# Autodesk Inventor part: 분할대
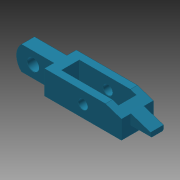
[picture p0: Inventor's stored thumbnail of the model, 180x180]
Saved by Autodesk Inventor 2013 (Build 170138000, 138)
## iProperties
Created: 2016-11
Part Number: 분할대
Material: 강철, 연강
Document SubType Name: Modeling
Designer: mduedu
Density: 1 g/cm^3
Author: mduedu
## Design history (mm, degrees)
sketch "스케치1"
  geometry: L1 (32.5, 13.5)-(-32.5, 13.5); L2 (-32.5, 13.5)-(-32.5, -13.5); L3 (-32.5, -13.5)-(32.5, -13.5); L4 (32.5, -13.5)-(32.5, 13.5); L5 (24, 7.5)-(-24, 7.5); L6 (-24, 7.5)-(-24, -7.5); L7 (-24, -7.5)-(24, -7.5); L8 (24, -7.5)-(24, 7.5); L9 (24, 0)-(-24, 0); L10 (0, -13.5)-(0, 13.5); 4 further points
  constraints: 20 end point, 7 midpoint, 4 parallel, 2 coincident, 2 horizontal, 2 perpendicular, 1 horizontal alignment
  dimensions: "d0" = 15 distance of L5.end L6.end; "d2" = 27 distance between parallel lines of L1 L3; "d3" = 48 distance of L5.start L5.end; "d4" = 65 distance of L1.start L1.end
extrude "돌출1" new body sketch "스케치1" distance "d5" = 20; taper "d6" = 0 deg
sketch "스케치2"
  geometry: L1 (0, 0)-(65, 0) reference; L2 (65, 0)-(65, 20) reference; L3 (0, 20)-(65, 20) reference; L4 (0, 0)-(0, 20) reference; L5 (32.5, 0)-(32.5, 20); C1 r 4 at (32.5, 10)
  constraints: 2 end point, 2 midpoint, 1 centre point
  dimensions: "d7" = 8 diameter of C1
extrude "돌출2" cut sketch "스케치2" stored distance "d8" = 20; taper "d9" = 0 deg
chamfer "모따기1" distance "d10" = 0.2; stored, may be unused: second distance "d11" = 2, angle "d12" = 45 deg
sketch "스케치3"
  geometry: L1 (-32.5, 0)-(-32.5, 20) reference; L2 (-32.5, 20)-(-59.798, 20); L3 (-64, 20)-(-64, 0); L4 (-64, 0)-(-59.798, 0); L5 (-32.5, 0)-(-32.5, 20); L6 (-59.798, 20)-(-64, 20); L7 (-59.798, 0)-(-32.5, 0); C1 r 4.2 at (0, 10) reference; C2 r 5 at (-50, 10); A1 r 14 centre (-50, 10) between (-59.798, 20) and (-59.798, 0); 1 further point
  constraints: 12 end point, 5 parallel, 2 centre point, 2 horizontal, 2 perpendicular, 2 point on circle, 1 coincident, 1 horizontal alignment, 1 tangent
  dimensions: "d13" = 64 distance from line of L3 C1.centre; "d14" = 14 radius of A1; "d15" = 10 diameter of C2
extrude "돌출3" join sketch "스케치3" stored distance "d16" = 11; taper "d17" = 0 deg
sketch "스케치4"
  geometry: L1 (32.5, 0)-(32.5, 20) reference; L2 (32.5, 20)-(49, 20); L3 (49, 20)-(49, 6); L4 (49, 6)-(32.5, 6); L5 (32.5, 6)-(32.5, 20); L6 (32.5, 0)-(-32.5, 0) reference; 1 further point
  constraints: 8 end point, 2 parallel, 1 horizontal, 1 perpendicular
  dimensions: "d18" = 16.5 distance of L1.end L2.end; "d19" = 6 distance between parallel lines of L4 L6
extrude "돌출4" join sketch "스케치4" stored distance "d20" = 11; taper "d21" = 0 deg
chamfer "모따기2" distance "d22" = 30; stored, may be unused: second distance "d23" = 10, angle "d24" = 45 deg
chamfer "모따기3" distance "d25" = 1; stored, may be unused: second distance "d26" = 10, angle "d27" = 45 deg
chamfer "모따기4" distance "d28" = 0.2; stored, may be unused: second distance "d29" = 10, angle "d30" = 45 deg
node "솔리드1"
node "투영된 루프1"
